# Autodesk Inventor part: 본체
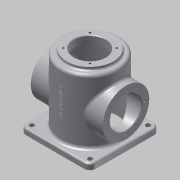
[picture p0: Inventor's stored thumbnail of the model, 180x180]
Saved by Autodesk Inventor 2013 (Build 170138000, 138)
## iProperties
Created: 2015-10
Part Number: 본체
Material: 알루미늄 6061
Document SubType Name: Modeling
Designer: user-11
Density: 2.71 g/cm^3
Mass: 985.997 g
Surface Area: 1037.35 cm^2
Volume: 363.836 cm^3
Author: user-11
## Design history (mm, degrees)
sketch "스케치1"
  geometry: L1 (-60, -60)-(60, -60); L2 (60, -60)-(60, 60); L3 (60, 60)-(-60, 60); L4 (-60, 60)-(-60, -60); 1 further point
  constraints: 8 end point, 2 parallel, 1 horizontal, 1 perpendicular
  dimensions: "d0" = 120 distance of L1.start L1.end; "d2" = 120 distance of L1.end L2.end; "d3" = 60 distance from line of point (0, 0) L1; "d4" = 60 distance from line of L2 point (0, 0)
extrude "돌출1" new body sketch "스케치1" distance "d5" = 10; taper "d6" = 0 deg
sketch "스케치2"
  geometry: C1 r 50 at (0, 0); 1 further point
  constraints: 1 centre point, 1 coincident
  dimensions: "d7" = 100 diameter of C1
extrude "돌출2" join sketch "스케치2" distance "d9" = 110; taper "d10" = 0 deg
node "작업 평면1"
sketch "스케치4"
  geometry: C1 r 50 at (0, 0) reference; C2 r 40 at (0, 0)
  constraints: 1 centre point, 1 coincident
  dimensions: "d17" = 80 diameter of C2
extrude "돌출4" join sketch "스케치4" distance "d19" = 5; taper "d20" = 0 deg
sketch "스케치5"
  geometry: C1 r 40 at (0, 0) reference; C2 r 27 at (0, 0)
  constraints: 1 centre point, 1 coincident
  dimensions: "d21" = 54 diameter of C2
extrude "돌출5" cut sketch "스케치5" distance "d23" = 13; taper "d24" = 0 deg
sketch "스케치6"
  geometry: C1 r 27 at (0, 0) reference; C2 r 45 at (0, 0)
  constraints: 1 centre point, 1 coincident
  dimensions: "d25" = 90 diameter of C2
extrude "돌출6" cut sketch "스케치6" distance "d27" = 112; taper "d28" = 0 deg
sketch "스케치10" dims "d57" = 65
  geometry: L1 (32.5, 0)-(-32.5, 0); L2 (0, 32.5)-(0, -32.5); L3 (0, 0)-(-22.981, 22.981); L4 (0, 0)-(-22.981, -22.981); L5 (0, 0)-(22.981, -22.981); L6 (0, 0)-(22.981, 22.981); C1 r 27 at (0, 0) reference
  constraints: 12 end point, 4 perpendicular, 1 horizontal, 10 other
  dimensions: "d59" = 0 distance of C1.centre L3.start; "d60" = 0 distance from line of C1.centre L2; "d61" = 0 distance from line of C1.centre L1; "d62" = 45 deg angle of L6 L1
hole "구멍3" sketch "스케치10" at (-22.981, 22.981), (22.981, 22.981), (22.981, -22.981), (-22.981, -22.981) diameter "d63" = 3.242; stored, may be unused: countersink angle "d67" = 90 deg, drill point angle "d69" = 118 deg; dims "d64" = 8, "d65" = 4, "d66" = 2, "d68" = 10
fillet "모깎기1" dims "d70" = 10
sketch "스케치11"
  geometry: C1 r 4 at (-50, -50); C2 r 4 at (50, -50); C3 r 4 at (50, 50); C4 r 4 at (-50, 50); A1 r 10 centre (-50, 50) between (-50, 60) and (-60, 50) reference; A2 r 10 centre (-50, -50) between (-60, -50) and (-50, -60) reference; A3 r 10 centre (50, -50) between (50, -60) and (60, -50) reference; A4 r 10 centre (50, 50) between (60, 50) and (50, 60) reference
  constraints: 4 centre point, 3 coincident
  dimensions: "d71" = 8 diameter of C1; "d73" = 0 distance of A3.centre C2.centre; "d74" = 0 distance of A3.centre C2.centre; "d75" = 8 diameter of C4; "d76" = 8 diameter of C3; "d77" = 8 diameter of C2
extrude "돌출8" cut sketch "스케치11" stored distance "d78" = 112; taper "d79" = 0 deg
fillet "모깎기2" dims "d80" = 3
fillet "모깎기5" dims "d83" = 5
fillet "모깎기6" dims "d84" = 5
fillet "모깎기7" dims "d85" = 3
chamfer "모따기1" distance "d86" = 3; stored, may be unused: second distance "d87" = 2, angle "d88" = 45 deg
node "작업 평면2"
sketch "스케치12"
  geometry: L1 (-6.946, 39.515)-(-6.946, 100.485); L2 (-6.946, 100.485)-(6.946, 100.485); L3 (6.946, 100.485)-(6.946, 39.515); L4 (6.946, 39.515)-(-6.946, 39.515); L5 (0, 39.515)-(0, 100.485); L6 (-6.946, 70)-(6.946, 70); L7 (0, 0)-(0, 149.644)
  constraints: 6 end point, 4 midpoint, 1 vertical, 2 other
  dimensions: "d99" = 70 distance from line of L7.start L6; "d100" = 0 distance from line of L7.start L5; "d103" = 0 distance between parallel lines of L7 L5
feature "엠보싱1" sketch "스케치12" dims "d0" = 120, "d2" = 120, "d3" = 60, "d4" = 60, "d104" = 0.5, "d105" = 0
chamfer "모따기3" distance "d106" = 1; stored, may be unused: second distance "d107" = 2, angle "d108" = 45 deg
node "작업 평면6"
sketch "스케치13"
  geometry: C1 r 40 at (0, 60); 1 further point
  constraints: 1 centre point
  dimensions: "d110" = 80 diameter of C1; "d112" = 60 distance of point (0, 0) C1.centre; "d114" = 0 horizontal distance of point (0, 0) C1.centre
extrude "돌출9" join sketch "스케치13" distance "d115" = 40; taper "d116" = 0 deg
sketch "스케치14"
  geometry: C1 r 45 at (0, 0) reference
extrude "돌출10" cut sketch "스케치14" distance "d117" = 112; taper "d118" = 0 deg
sketch "스케치15"
  geometry: C1 r 40 at (0, 0) reference; C2 r 27 at (0, 0); 1 further point
  constraints: 1 centre point, 1 coincident
  dimensions: "d119" = 54 diameter of C2
extrude "돌출11" cut sketch "스케치15" stored distance "d121" = 112; taper "d122" = 0 deg
sketch "스케치16" dims "d123" = 65
  geometry: L1 (0, 0)-(-32.5, 0); C1 r 40 at (0, 0) reference; 1 further point
  constraints: 2 end point, 1 coincident, 1 horizontal, 1 horizontal alignment, 2 other
hole "구멍4" sketch "스케치16" at (-32.5, 0) diameter "d125" = 3.242; stored, may be unused: countersink angle "d129" = 90 deg, drill point angle "d131" = 118 deg; dims "d126" = 8, "d127" = 4, "d128" = 2, "d130" = 10
fillet "모깎기8" dims "d135" = 5
sketch "스케치17"
  geometry: C1 r 45 at (0, 0) reference
extrude "돌출12" cut sketch "스케치17" distance "d136" = 112; taper "d137" = 0 deg
fillet "모깎기9" dims "d138" = 3
chamfer "모따기4" distance "d139" = 1; stored, may be unused: second distance "d140" = 2, angle "d141" = 45 deg
node "솔리드1"
mirror "대칭2"
pattern_circular "원형 패턴3" dims angle "d133" = 360 deg
mirror "대칭3"
other parameters: "d11" = 62.5, "d92" = -60.75, "d109" = 62
